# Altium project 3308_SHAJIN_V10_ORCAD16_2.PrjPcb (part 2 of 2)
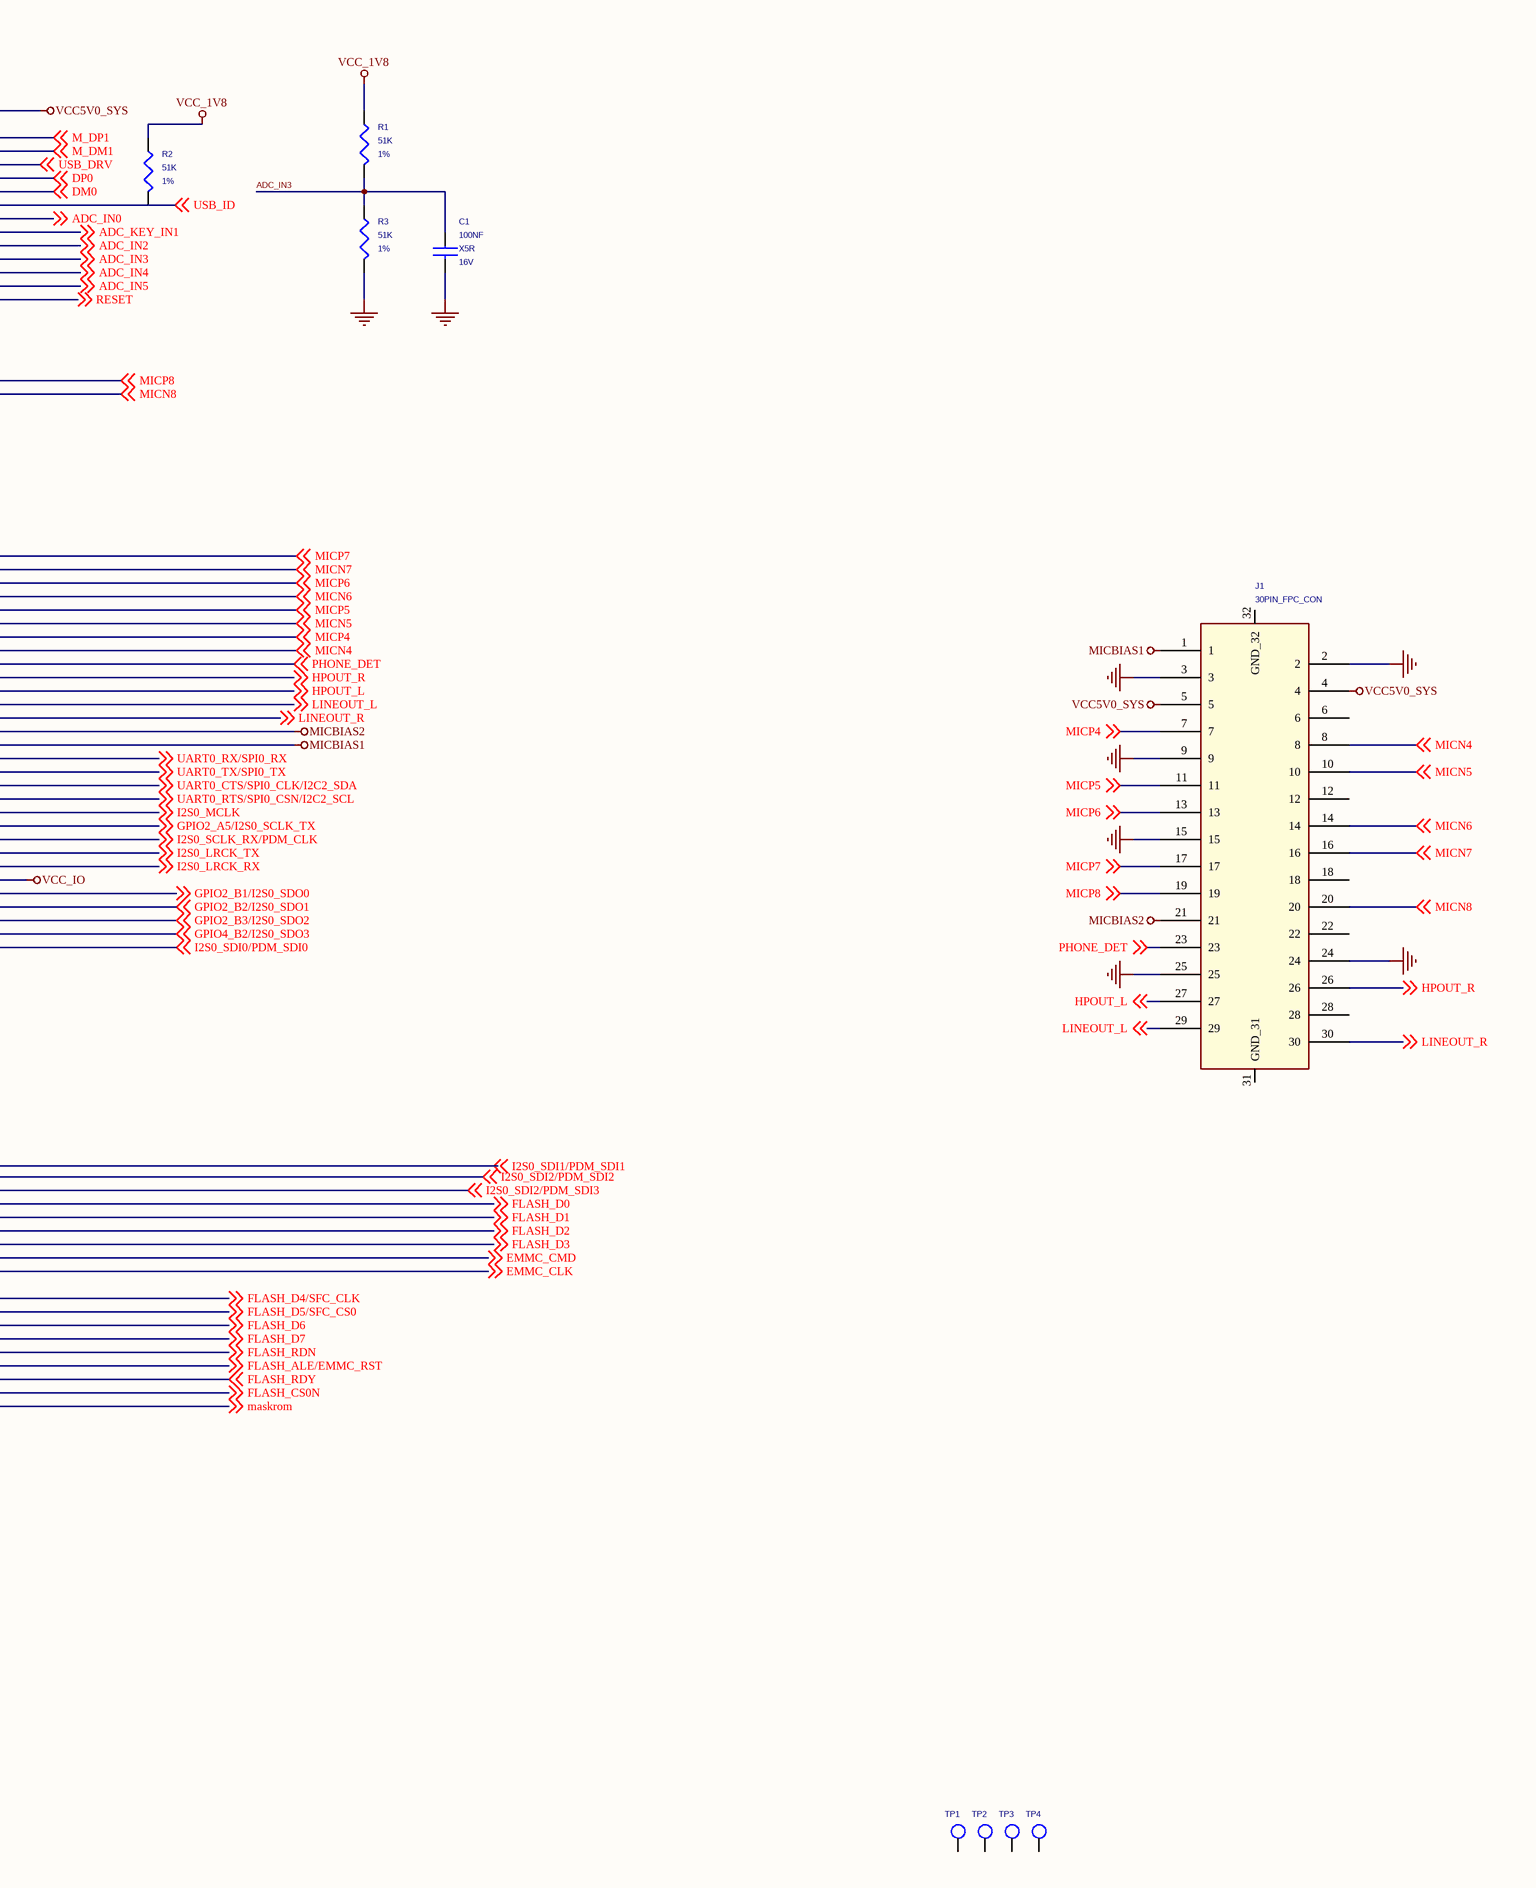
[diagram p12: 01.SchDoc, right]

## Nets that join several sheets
5V: 12 (10 pins), 08 (R61.2), 07 (6 pins), 05 (R28.1), 03 (5 pins), 01 (J1.4 J1.5 U1.111 U1.112)
ABLU0: 12 (42 pins), 11 (17 pins), 10 (21 pins), 09 (19 pins), 08 (C32.1 C33.1 C34.1 R57.1), 07 (17 pins), 05 (24 pins), 04 (14 pins), 03 (35 pins), 02 (8 pins), 01 (15 pins)
DC-12V: 07 (R40.2), 05 (5 pins)
VCC3V3_SYS: 11 (7 pins), 10 (11 pins), 09 (C49.1 C50.1 J6.3), 03 (R4.1 R9.1 R19.2), 02 (RD1.2 U2.3), 01 (U1.66)
VCC_1V8: 11 (R79.1), 09 (C51.1 C52.1 J6.6), 05 (R32.1), 01 (R1.1 R2.1 U1.94)
VCC_SD: 04 (C16.1 C17.1 J3.4), 01 (U1.116)
ABLU2: 03 (FP1.23), 01 (U1.33)
ABLU3: 03 (FP1.24), 01 (U1.34)
ABLU4: 03 (FP1.25), 01 (U1.35)
ABLU5: 03 (FP1.26), 01 (U1.36)
ABLU6: 03 (FP1.27), 01 (U1.37)
ABLU7: 03 (FP1.28), 01 (U1.38)
ADC_HW_ID1: 09 (J6.7), 07 (CON1.7), 01 (C1.1 R1.2 R3.1 U1.99)
ADC_IN0: 07 (CON1.8), 05 (C26.1 J11.2 R32.2 SW2.2), 01 (U1.102)
ADC_IN2: 07 (CON1.12), 01 (U1.100)
ADC_IN4: 07 (CON1.9), 01 (U1.98)
ADC_IN5: 07 (CON1.11), 01 (U1.97)
ADC_KEY_IN1: 09 (J6.8), 07 (CON1.10), 01 (U1.101)
AGRN2: 03 (FP1.15), 01 (U1.26)
AGRN3: 03 (FP1.16), 01 (U1.28)
AGRN4: 03 (FP1.17), 01 (U1.29)
AGRN5: 03 (FP1.18), 01 (U1.30)
AGRN6: 03 (FP1.19), 01 (U1.31)
AGRN7: 03 (FP1.20), 01 (U1.32)
ARED2: 03 (FP1.7), 01 (U1.21)
ARED3: 03 (FP1.8), 01 (U1.22)
ARED4: 03 (FP1.9), 01 (U1.23)
ARED5: 03 (FP1.10), 01 (U1.24)
ARED6: 03 (FP1.11), 01 (U1.25)
ARED7: 03 (FP1.12), 01 (U1.27)
B_DM3: 12 (U14.6), 08 (U7.7)
B_DP3: 12 (U14.7), 08 (U7.8)
DC12V_ADC: 07 (U6.12), 05 (R34.1 R35.2)
DCLK: 03 (FP1.30), 01 (U1.17)
DENA: 03 (FP1.34), 01 (U1.20)
DHS: 03 (FP1.32), 01 (U1.19)
DISP_EN: 03 (R8.2), 01 (U1.14)
DM4: 12 (U14.4), 07 (R45.2)
DP4: 12 (U14.5), 07 (R44.2)
DVS: 03 (FP1.33), 01 (U1.18)
EMMC_CLK: 11 (U12.W6), 01 (U1.52)
EMMC_CMD: 11 (U12.W5), 01 (U1.53)
EMMC_D0: 11 (U12.H3), 01 (U1.57)
EMMC_D1: 11 (U12.H4), 01 (U1.56)
EMMC_D2: 11 (U12.H5), 01 (U1.55)
EMMC_D3: 11 (U12.J2), 01 (U1.54)
EMMC_D4: 11 (U12.J3), 01 (U1.51)
EMMC_D5: 11 (U12.J4), 01 (U1.50)
EMMC_D6: 11 (U12.J5), 01 (U1.49)
EMMC_D7: 11 (U12.J6), 01 (U1.48)
FLASH_ALE/EMMC_RST: 11 (R77.1), 01 (U1.46)
FLASH_CS0N: 10 (R64.2 R66.2), 01 (U1.44)
FLASH_RDY: 10 (R63.2 R65.2), 01 (U1.45)
GPIO0_A1: 07 (CON1.5), 01 (U1.3)
GPIO0_A5: 07 (R48.2), 01 (U1.4)
GPIO0_A6: 07 (CON1.4), 01 (U1.5)
GPIO0_A7: 07 (CON1.6), 01 (U1.6)
GPIO0_B0: 02 (RD2.2), 01 (U1.7)
GPIO0_B1: 03 (R14.1), 01 (U1.8)
GPIO0_B2: 03 (R12.1), 01 (U1.9)
GPIO0_B6: 03 (R6.2), 01 (U1.12)
GPIO0_B7/PWM2/I2C3_SDA: 12 (R81.1), 01 (U1.13)
GPIO0_C2: 03 (R16.2 U4.4), 01 (U1.16)
GPIO2_A5/I2S0_SCLK_TX: 07 (CON1.16), 01 (U1.70)
GPIO2_B1/I2S0_SDO0: 07 (CON1.22), 01 (U1.65)
GPIO2_B2/I2S0_SDO1: 07 (CON1.24), 01 (U1.64)
GPIO2_B3/I2S0_SDO2: 07 (CON1.26), 01 (U1.63)
GPIO4_B2/I2S0_SDO3: 07 (CON1.28), 01 (U1.62)
GPIO4_D6_D: 07 (CON1.1), 01 (U1.1)
I2C0_SCL: 10 (R75.2), 07 (5 pins), 03 (R11.1), 01 (U1.11)
I2C0_SDA: 10 (R76.2), 07 (5 pins), 03 (R13.1), 01 (U1.10)
I2C2_SCL: 09 (J6.30), 01 (U1.72)
I2C2_SDA: 09 (J6.29), 01 (U1.73)
I2S0_LRCK_RX: 07 (CON1.15), 01 (U1.67)
I2S0_LRCK_TX: 07 (CON1.13), 01 (U1.68)
I2S0_MCLK: 07 (CON1.14), 01 (U1.71)
I2S0_SCLK_RX/PDM_CLK: 09 (ED1.1 J6.10), 07 (CON1.18), 01 (U1.69)
I2S0_SDI0/PDM_SDI0: 09 (J6.22), 01 (U1.61)
I2S0_SDI1/PDM_SDI1: 09 (ED2.2 J6.23), 01 (U1.60)
I2S0_SDI2/PDM_SDI2: 09 (ED3.1 J6.24), 01 (U1.59)
I2S0_SDI2/PDM_SDI3: 09 (ED4.2 J6.25), 01 (U1.58)
M_DM1: 12 (U14.15), 01 (U1.109)
M_DP1: 12 (U14.16), 01 (U1.110)
maskrom: 05 (SW3.2), 01 (U1.43)
MIC_LED_EN: 09 (J6.28), 01 (U1.47)
PWM3/GPIO0_C0/IR_RX: 03 (R17.1 R19.1), 01 (U1.15)
RESET: 05 (J11.1 SW4.2), 01 (U1.96)
SDMMC_CLK: 04 (D9.1 J3.5), 01 (U1.117)
SDMMC_CMD: 04 (R23.1), 01 (U1.115)
SDMMC_D0: 04 (R24.1), 01 (U1.118)
SDMMC_D1: 04 (R25.1), 01 (U1.119)
SDMMC_D2/UART2_RX_M1: 04 (R21.1), 01 (U1.113)
SDMMC_D3/UART2_TX_M1: 04 (R22.1), 01 (U1.114)
SDMMC_DET: 04 (R26.1), 01 (U1.120)
SPDIF_TX: 07 (CON1.3), 01 (U1.2)
SPI2_CLK: 02 (RW5.2), 01 (U1.41)
SPI2_CS: 02 (RW2.2), 01 (U1.42)
SPI2_RX/UART2_RX_M0: 02 (RW4.2), 01 (U1.39)
SPI2_TX/UART2_TX_M0: 02 (RW3.2), 01 (U1.40)
UART0_RX/SPI0_RX: 07 (R43.1), 01 (U1.75)
UART0_TX/SPI0_TX: 07 (R42.1), 01 (U1.74)
USB-DM0: 12 (D17.1 J10.A7 J10.B7), 01 (U1.105)
USB-DP0: 12 (D16.1 J10.A6 J10.B6), 01 (U1.106)
USB_DRV: 12 (R82.2 U13.4), 01 (U1.108)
